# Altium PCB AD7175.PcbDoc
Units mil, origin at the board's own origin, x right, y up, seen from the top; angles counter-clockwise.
Board outline 2780 x 1750 mil, 2 copper layers (Top Layer, Bottom Layer); 97 components, 55 nets, 296 pads, 449 vias.
Unrouted connection lines stored in the file: 60.
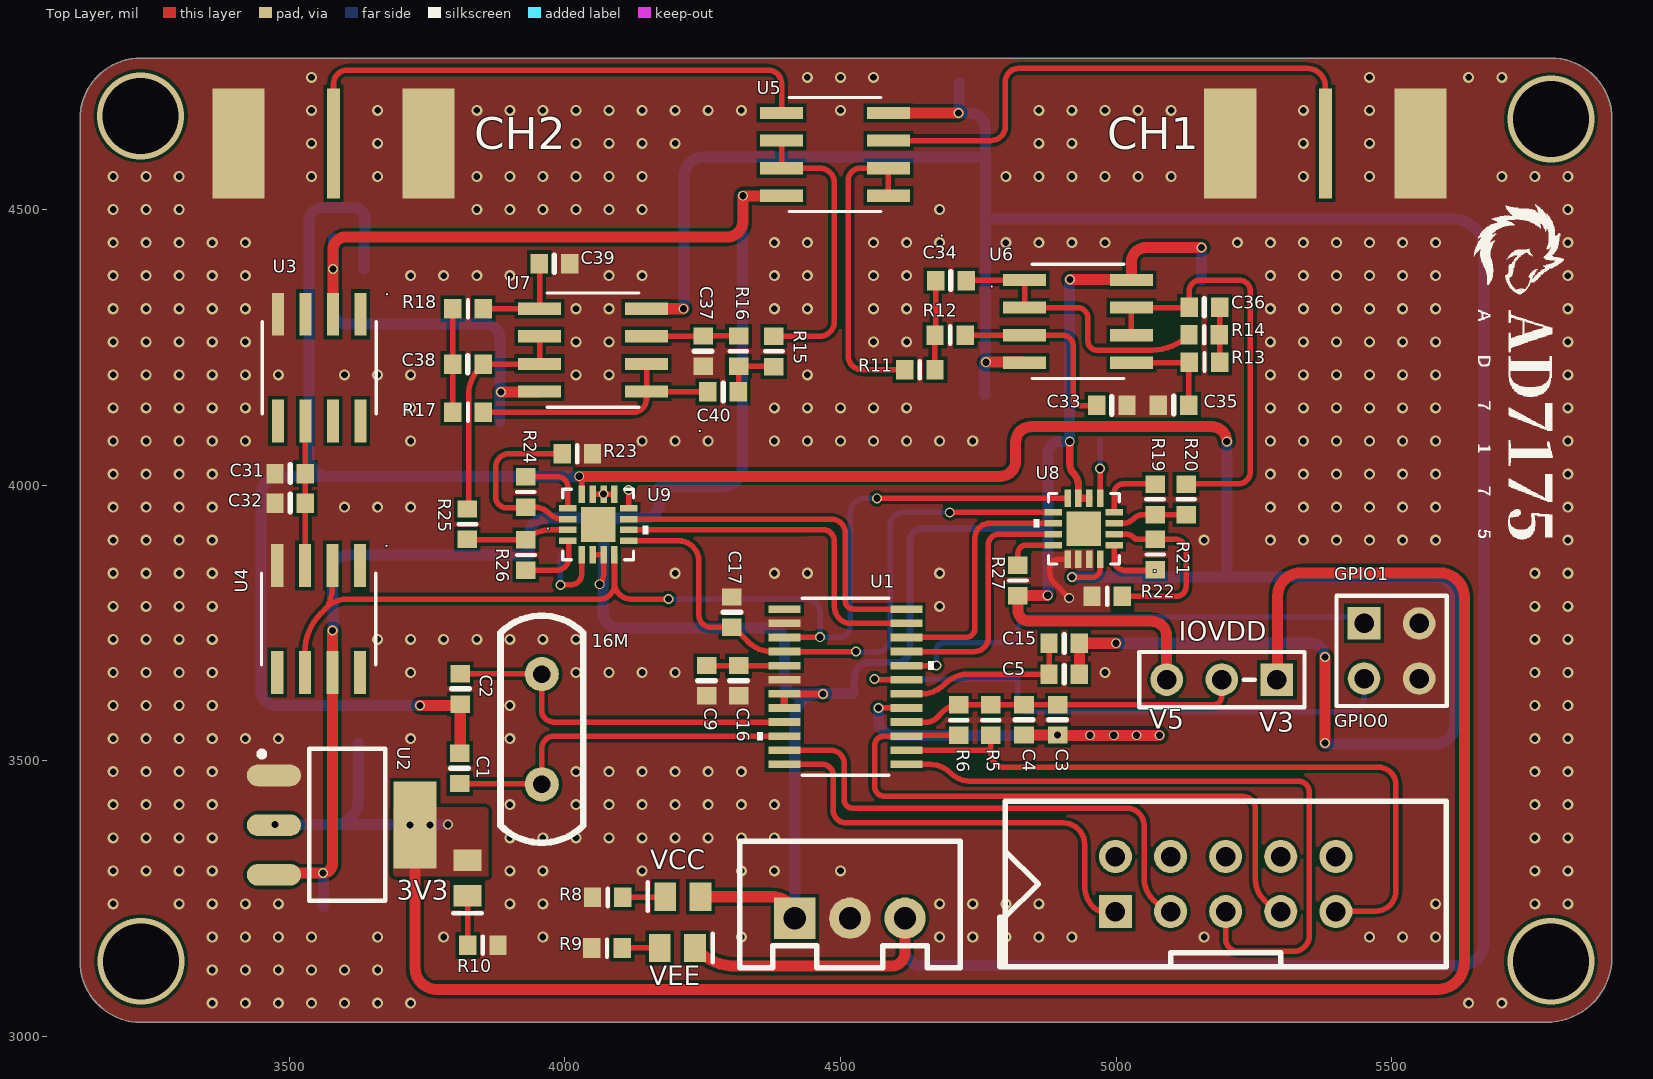
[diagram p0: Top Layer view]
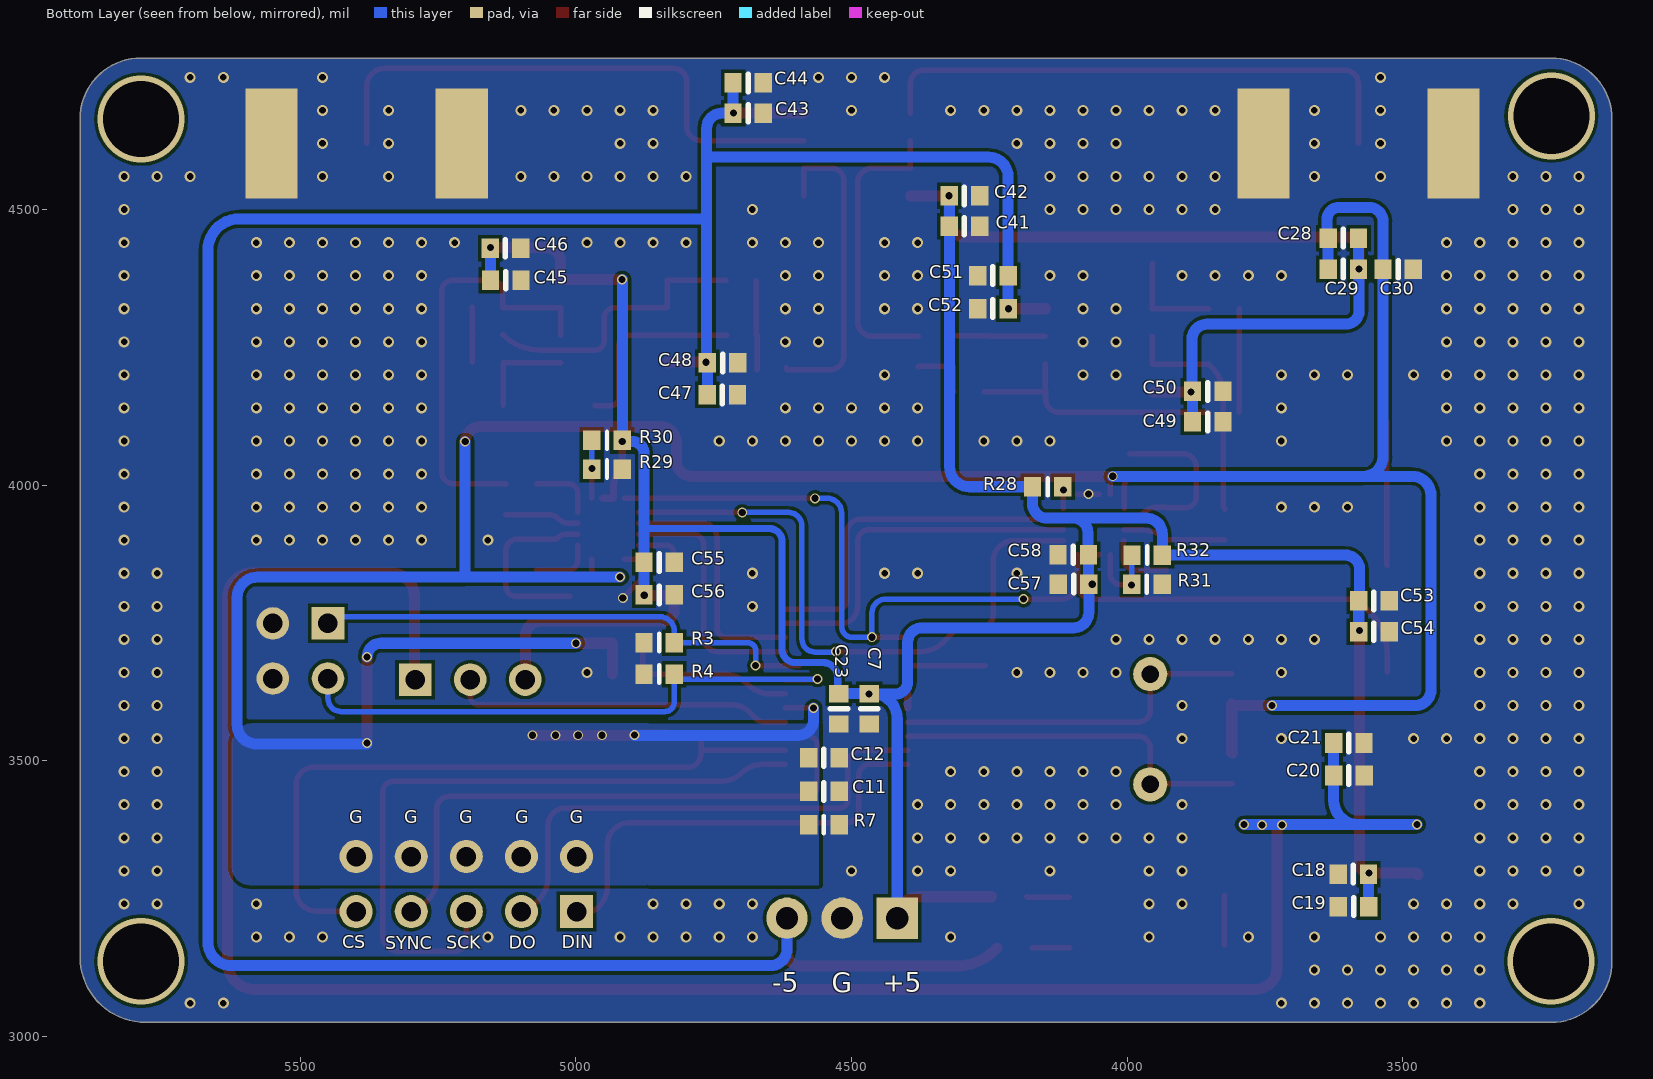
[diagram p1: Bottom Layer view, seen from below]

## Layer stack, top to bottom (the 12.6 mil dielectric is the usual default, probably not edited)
Top Solder: solder mask 0.4, Solder Resist, Dk 3.5
Top Layer: signal copper 1.4
Dielectric 1: dielectric 12.6, FR-4, Dk 4.8
Bottom Layer: signal copper 1.4
Bottom Solder: solder mask 0.4, Solder Resist, Dk 3.5

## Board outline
3120,3135.83 ccw(c3230.83,3135.83) 3230.83,3025 4085,3025 5781.01,3025 ccw(c5781.01,3143.99) 5900,3143.99 5900,4664.17 ccw(c5789.17,4664.17) 5789.17,4775 3230.83,4775 ccw(c3230.83,4664.17) 3120,4664.17

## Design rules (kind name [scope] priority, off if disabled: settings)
Clearance [All] p1: gap=6 ignorepadtopadclearanceinfootprint=FALSE except(0: Arc-Hole Track-Hole SMDPad-Hole THPad-Hole Via-Hole Fill-Hole Poly-Hole Region-Hole Text-Hole; 5: Arc-SMDPad Arc-THPad Track-SMDPad Track-THPad SMDPad-SMDPad SMDPad-THPad THPad-THPad)
PolygonConnect [All] p1: connectstyle=Direct reliefconductorwidth=10 reliefentries=4 polygonreliefangle="90 Angle" airgapwidth=10
RoutingVias [All] p1: holewidth=28 width=50 viastyle="Through Hole" minholewidth=28 minwidth=50 maxholewidth=28 maxwidth=50
SolderMaskExpansion [All] p1: expansion=4 istentingtop=FALSE
Width [All] p1: maxlimit=100 minlimit=10 preferedwidth=10
30 further rules are at their usual default settings.

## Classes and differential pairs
component class reference: C28 C29 C30 C31 C32 C53 C54 U3 U4
component class power: C7 C18 C19 C20 C21 C23 R8 R9 R10 U2
component class filter: C33 C34 C35 C36 C37 C38 C39 C40 C45 C46 C47 C48 C49 C50 C51 C52 R11 R12 R13 R14 R15 R16 R17 R18 U6 U7
component class fda: C55 C56 C57 C58 R19 R20 R21 R22 R23 R24 R25 R26 R27 R28 R29 R30 R31 R32 U8 U9
component class core: C1 C2 C3 C4 C5 C9 C11 C12 C15 C16 C17 C41 C42 C43 C44 CH1 CH2 IOVDD R3 R4 R5 R6 R7 U1 U5

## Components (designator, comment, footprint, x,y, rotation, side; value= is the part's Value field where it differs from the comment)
3V3 "LED" Led-0805_L 3823,3287 r270 top (schematic designator LED3)
16M "XTAL" XTAL-PB2-DIP 3966,3547 r270 top value=16M (schematic designator Y1)
C1 "Cap-S" C0603-L 3809,3486 r90 top value=20pF
C2 "Cap-S" C0603-L 3810,3630 r270 top value=20pF
C3 "Cap-S" C0603-L 4894,3574 r90 top value=1uF
C4 "Cap-S" C0603-L 4833,3574 r90 top value=100nF
C5 "Cap-S" C0603-L 4906,3657 r180 top value=1uF
C7 "Cap-S" C0603-L 4468,3594 r270 bottom value=1uF
C9 "Cap-S" C0603-L 4257,3645 r90 top value=1uF
C11 "Cap-S" C0603-L 4550,3444 r180 bottom value=1uF
C12 "Cap-S" C0603-L 4550,3505 r180 bottom value=100nF
C15 "Cap-S" C0603-L 4906,3713 r180 top value=100nF
C16 "Cap-S" C0603-L 4315,3645 r90 top value=100nF
C17 "Cap-S" C0603-L 4303,3769.44 r270 top value=100nF
C18 "Cap-S" C0603-L 3589.44,3294 r180 bottom value=1uF
C19 "Cap-S" C0603-L 3588.88,3235 r180 bottom value=100nF
C20 "Cap-S" C0603-L 3597.44,3473 r0 bottom value=100nF
C21 "Cap-S" C0603-L 3597.56,3532 r0 bottom value=1uF
C23 "Cap-S" C0603-L 4523,3594 r270 bottom value=100nF
C28 "Cap-S" C0603-L 3607.44,4448 r180 bottom value=4.7uF
C29 "Cap-S" C0603-L 3607.44,4392 r180 bottom value=100nF
C30 "Cap-S" C0603-L 3508,4392 r0 bottom value=100nF
C31 "Cap-S" C0603-L 3501.44,4021 r0 top value=4.7uF
C32 "Cap-S" C0603-L 3501.44,3967 r0 top value=100nF
C33 "Cap-S" C0603-L 4992.44,4145 r180 top value=13pF
C34 "Cap-S" C0603-L 4700.44,4371 r0 top value=130pF
C35 "Cap-S" C0603-L 5104.44,4145 r0 top value=10pF
C36 "Cap-S" C0603-L 5160.44,4323 r180 top value=119pF
C37 "Cap-S" C0603-L 4251,4243 r90 top value=13pF
C38 "Cap-S" C0603-L 3824,4219 r0 top value=119pF
C39 "Cap-S" C0603-L 3981,4402 r180 top value=10pF
C40 "Cap-S" C0603-L 4287,4169 r180 top value=130pF
C41 "Cap-S" C0603-L 4295,4470 r0 bottom value=100nF
C42 "Cap-S" C0603-L 4295,4525 r0 bottom value=1uF
C43 "Cap-S" C0603-L 4687.44,4675 r0 bottom value=100nF
C44 "Cap-S" C0603-L 4687.44,4730 r0 bottom value=1uF
C45 "Cap-S" C0603-L 5127.44,4372 r0 bottom value=100nF
C46 "Cap-S" C0603-L 5128,4430 r0 bottom value=1uF
C47 "Cap-S" C0603-L 4734.44,4164 r0 bottom value=100nF
C48 "Cap-S" C0603-L 4734,4222 r0 bottom value=1uF
C49 "Cap-S" C0603-L 3853.56,4115 r0 bottom value=100nF
C50 "Cap-S" C0603-L 3853.56,4170 r0 bottom value=1uF
C51 "Cap-S" C0603-L 4243.44,4380 r180 bottom value=100nF
C52 "Cap-S" C0603-L 4243.44,4320 r180 bottom value=1uF
C53 "Cap-S" C0603-L 3552,3790 r0 bottom value=100nF
C54 "Cap-S" C0603-L 3552,3734 r0 bottom value=1uF
C55 "Cap-S" C0603-L 4849,3860 r0 bottom value=100nF
C56 "Cap-S" C0603-L 4849,3801 r0 bottom value=1uF
C57 "Cap-S" C0603-L 4097,3820 r180 bottom value=100nF
C58 "Cap-S" C0603-L 4097.61,3873.31 r180 bottom value=1uF
CH1 "SMA" SMA1 5380,4620 r270 top
CH2 "SMA" SMA1 3580,4620 r270 top
GPIO1 "Header 2X2" HDR2X2 5450,3749 r270 top (schematic designator GPIO)
IOVDD "Jumper" JUMPER1x3 5192,3647 r180 top
POWER "Power-3P" SIPA03 4417,3214 r0 top
R3 "R" R0603-L 4849,3714 r180 bottom value=10K
R4 "R" R0603-L 4849,3657 r180 bottom value=10K
R5 "R" R0603-L 4773,3573.56 r90 top value=10K
R6 "R" R0603-L 4715,3573.56 r90 top value=10K
R7 "R" R0603-L 4550.12,3384 r0 bottom value=0R
R8 "R" R0603-L 4077.44,3252 r180 top value=1K
R9 "R" R0603-L 4076.44,3160 r180 top value=1K
R10 "R" R0603-L 3851,3165 r0 top value=600R
R11 "R" R0603-L 4644,4209 r0 top value=6.25K
R12 "R" R0603-L 4699,4272 r0 top value=177K
R13 "R" R0603-L 5160.44,4223 r0 top value=31.9K
R14 "R" R0603-L 5160,4273 r180 top value=31.9K
R15 "R" R0603-L 4379,4242.56 r270 top value=6.25K
R16 "R" R0603-L 4315,4243 r90 top value=177K
R17 "R" R0603-L 3824,4132 r0 top value=31.9K
R18 "R" R0603-L 3824,4320 r180 top value=31.9K
R19 "R" R0603-L 5071,3974 r90 top value=1K
R20 "R" R0603-L 5127,3974 r270 top value=1K
R21 "R" R0603-L 5071,3874 r270 top value=1K
R22 "R" R0603-L 4984,3798 r0 top value=1K
R23 "R" R0603-L 4022.44,4057 r180 top value=1K
R24 "R" R0603-L 3929,3987.56 r90 top value=1K
R25 "R" R0603-L 3823,3929 r270 top value=1K
R26 "R" R0603-L 3929,3873 r270 top value=1K
R27 "R" R0603-L 4822,3827 r270 top value=0R
R28 "R" R0603-L 4144,3997 r0 bottom value=0R
R29 "R" R0603-L 4943.56,4029 r180 bottom value=0R
R30 "R" R0603-L 4943.56,4081 r180 bottom value=0R
R31 "R" R0603-L 3964,3820 r180 bottom value=0R
R32 "R" R0603-L 3963.56,3873 r180 bottom value=0R
SPI "DC-10P" DC-10P 5198.94,3226 r180 top
U1 "AD7175-2BRUZ" RU_24_ADI 4509,3634 r0 top
U2 "AMS1117" SOT-223 3597,3383 r270 top
U3 "ADR4540ARZ" R_8_ADI 3554,4213 r270 top
U4 "AD8628ARZ" R_8_ADI 3553,3757 r270 top
U5 "ADA4084-2ARZ" R_8_ADI 4490,4600 r180 top
U6 "ADA4084-2ARZ" R_8_ADI 4931,4297 r0 top
U7 "ADA4084-2ARZ" R_8_ADI 4051,4245 r180 top
U8 "ADA4945-1" CP_16_22 4941.53,3920.79 r180 top
U9 "ADA4945-1" CP_16_22 4060.21,3928.53 r0 top
VCC "LED" Led-0805_L 4214,3253 r180 top (schematic designator LED1)
VEE "LED" Led-0805_L 4204,3160 r0 top (schematic designator LED2)

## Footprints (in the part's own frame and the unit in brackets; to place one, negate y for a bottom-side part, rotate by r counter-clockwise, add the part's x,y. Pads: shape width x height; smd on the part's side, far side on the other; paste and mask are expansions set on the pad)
C0603-L [mm] "贴片电容0603 高密度"
  rect 0.8x0.9 smd: 1(-0.7,0) 2(0.7,0)
  silkscreen extent 0,-0.39 0,0.41, body extent -0.8,-0.4 0.8,0.41, height 0.88
CP_16_22 [mm]
  rect 0.805x0.3 smd paste+0 mask+0: 1(-1.402,0.75) 2(-1.402,0.25) 3(-1.402,-0.25) 4(-1.402,-0.75) 9(1.402,-0.75) 10(1.402,-0.25) 11(1.402,0.25) 12(1.402,0.75)
  rect 0.3x0.805 smd paste+0 mask+0: 5(-0.75,-1.402) 6(-0.25,-1.402) 7(0.25,-1.402) 8(0.75,-1.402) 13(0.75,1.402) 14(0.25,1.402) 15(-0.25,1.402) 16(-0.75,1.402)
  rect 1.6x1.6 smd paste-0.787 mask+0: 17(0,0)
  silkscreen extent -1.63,-1.63 2.31,1.63, body extent 0,0 0.25,0.25, height 0.25
DC-10P [mil]
  rect 60x60 hole 35.43: 1(200,0)
  round 60 hole 35.43: 2(100,0) 3(0,0) 4(-100,0) 5(-200,0) 6(-200,-100) 7(-100,-100) 8(0,-100) 9(100,-100) 10(200,-100)
  silkscreen extent -400,-200 410,100, body extent -401,-233 401,123, height 357
HDR2X2 [mm] "Connector; Header; 2x2 Position"
  rect 1.5x1.5 hole 0.9: 1(0,0)
  round 1.5 hole 0.9: 2(0,2.54) 3(2.54,0) 4(2.54,2.54)
  silkscreen extent -1.27,-1.27 3.81,3.81
JUMPER1x3 [mm]
  rect 1.5x1.5 hole 0.9: 1(-2.54,0)
  round 1.5 hole 0.9: 2(0,0) 3(2.54,0)
  silkscreen extent -3.81,-1.27 3.81,1.27, body extent -3.81,-1.27 3.81,1.3, height 9.26
Led-0805_L [mm] "贴片LED0805-高密度"
  rect 1x1.3 smd: 1(-0.813,0) 2(0.813,0)
  silkscreen extent 1.63,-0.66 1.63,0.66, body extent -1.03,-0.44 1.03,0.47, height 0.85
R0603-L [mm] "贴片电阻0603 高密度"
  rect 0.8x0.9 smd: 1(-0.7,0) 2(0.7,0)
  silkscreen extent 0,-0.39 0,0.41, body extent -0.81,-0.43 0.79,0.39, height 0.53
R_8_ADI [mil]
  rect 78x22 smd paste+0 mask+0: 1(-97,75) 2(-97,25) 3(-97,-25) 4(-97,-75) 5(97,-75) 6(97,-25) 7(97,25) 8(97,75)
  silkscreen extent -84,-103 84,104, body extent -122,-99 122,99, height 69
RU_24_ADI [mil]
  rect 58x14 smd paste+0 mask+0: 1(-111,140.75) 2(-111,115.16) 3(-111,89.57) 4(-111,63.98) 5(-111,38.39) 6(-111,12.8) 7(-111,-12.8) 8(-111,-38.39) 9(-111,-63.98) 10(-111,-89.57) 11(-111,-115.16) 12(-111,-140.75) 13(111,-140.75) 14(111,-115.16) 15(111,-89.57) 16(111,-63.98) 17(111,-38.39) 18(111,-12.8) 19(111,12.8) 20(111,38.39) 21(111,63.98) 22(111,89.57) 23(111,115.16) 24(111,140.75)
  silkscreen extent -160,-160 160,160, body extent -126,-156 126,156, height 47
SIPA03 [mil]
  rect 75x75 hole 40: 1(0,0)
  round 75 hole 40: 2(100,0) 3(200,0)
  silkscreen extent -100,-90 300,140, body extent -96,-99 298,137, height 276
SMA1 [mil]
  rect 200x24 smd: 1(0,0)
  rect 200x95 smd: 2(0,-172.5) 2(0,172.5)
  rect 200x95 smd far side: 2(0,-172.5)
  rect 200x95 smd far side mask+4: 2(0,172.5)
  body extent -475,-187 87,187, height 171
SOT-223 [mm]
  oval 1x2.5 smd: 1(-2.29,-3.175) 2(0,-3.175) 3(2.29,-3.175)
  rect 4x2 smd: 2(0,3.325)
  silkscreen extent -3.52,-3.86 3.48,1.96, body extent -3.25,-3.2 3.25,3.76, height 1.66
XTAL-PB2-DIP [mil]
  round 62 hole 32: 1(-110,-8) 2(90,-8)
  silkscreen extent -216,-83 196,67, body extent -234,-99 212,85, height 142

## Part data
3V3 VCC VEE: "发光二极管"
16M: "晶振"
C1 C2 C3 C4 C5 C7 C9 C11 C12 C15 C16 C17 C18 C19 C20 C21 C23 C28 C29 C30 C31 C32 C33 C34 C35 C36 C37 C38 C39 C40 C41 C42 C43 C44 C45 C46 C47 C48 C49 C50 C51 C52 C53 C54 C55 C56 C57 C58: "贴片瓷片电容"
GPIO1: "Header, 2-Pin, Dual row"
IOVDD: library part Jumper1*3
POWER: "供电端子"
R3 R4 R5 R6 R7 R8 R9 R10 R11 R12 R13 R14 R15 R16 R17 R18 R19 R20 R21 R22 R23 R24 R25 R26 R27 R28 R29 R30 R31 R32: library part Res, "贴片电阻"
U1 U3 U4 U5 U6 U7: "No Description Available", Mfr_Name="Analog Devices Inc"

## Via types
v1: diameter 20, hole 12, Top Layer to Bottom Layer, 402 vias
v2: diameter 18, hole 13, Top Layer to Bottom Layer, 43 vias
v3: diameter 157.48, hole 137.8, Top Layer to Bottom Layer, 4 vias

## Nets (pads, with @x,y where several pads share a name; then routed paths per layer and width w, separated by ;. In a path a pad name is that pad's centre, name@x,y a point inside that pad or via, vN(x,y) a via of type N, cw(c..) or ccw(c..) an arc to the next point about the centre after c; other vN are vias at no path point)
3V3: 3V3.1 C20.2 C21.2 IOVDD.1 U2.2 | length 3903.6
  Top Layer w20: U2.2@3727.91,3383 3727.91,3124.09 ccw(c3767,3124.09) 3767,3085 5584,3085 ccw(c5584,3133) 5632,3133 5632,3796.57 ccw(c5587.91,3796.57) 5587.91,3840.66 5335.66,3840.66 ccw(c5335.66,3798) 5293,3798 5293,3648 cw(c5292,3648) IOVDD.1
  Bottom Layer w20: v2(3474,3384) 3581,3384 ; C21.2 3625,3532 C20.2 3625,3428 cw(c3581,3428) 3581,3384 ; v2(3788,3384) 3581,3384
  other v2: 3719,3383 3755,3383
AIN0: U1.21 U8.11 | length 460
  Top Layer w10: U1.21 4742.98,3697.98 ccw(c4742.98,3723) 4768,3723 4768,3891 cw(c4787.94,3891) 4787.94,3910.94 U8.11
AIN1: U1.22 U8.10 | length 454.9
  Top Layer w10: U1.22 4727.57,3723.57 ccw(c4727.57,3740) 4744,3740 4744,3904 cw(c4770.63,3904) 4770.63,3930.63 U8.10
AIN2: U1.23 U9.10 | length 653.1
  Top Layer w10: U9.10 4439,3918.69 4439,3919 4468,3919 cw(c4468,3898) 4489,3898 4489,3779.16 ccw(c4519.16,3779.16) 4519.16,3749 4620,3749 U1.23
AIN3: U1.24 U9.11 | length 650.7
  Top Layer w10: U9.11 4482.63,3938.37 cw(c4482.63,3912) 4509,3912 4509,3789.32 ccw(c4523.32,3789.32) 4523.32,3775 4620,3775 U1.24
AVSS: C7.2 C9.1 C11.2 C12.2 C16.1 C17.1 C18.1 C19.1 C20.1 C21.1 C23.2 C30.1 C31.1 C32.1 C33.1 C35.1 C37.1 C39.1 C41.1 C42.1 C43.1 C44.1 C45.1 C46.1 C47.1 C48.1 C49.1 C50.1 C51.1 C52.1 C53.1 C54.1 C55.1 C56.1 C57.1 C58.1 CH1.2 CH2.2 GPIO1.2 GPIO1.4 POWER.2 R3.1 R4.1 R7.1 R8.2 R9.2 R10.2 R22.1 R23.1 R29.2 R31.2 U1.2 U1.6 U2.1 U3.4 U4.4 U8.13 U8.14 U8.15 U9.13 U9.14 U9.15 | length 148.7
  Top Layer w10: U9.15 v2(4070.06,3983.74) U9.13 ; U8.13 4895.57,3865.57 ccw(c4895.57,3850) 4880,3850 4880,3840 ccw(c4904.14,3840) 4887.07,3822.93 v2(4915,3795)
  other v1: 3360,3060 3420,3060 3480,3060 3540,3060 3600,3060 3660,3060 3720,3060 5640,3060 5700,3060 3360,3120 3420,3120 3480,3120 3540,3120 3600,3120 3660,3120 3360,3180 3420,3180 3480,3180 3540,3180 3660,3180 3780,3180 3960,3180 4320,3180 4680,3180 4740,3180 4800,3180 4860,3180 4920,3180 5160,3180 5460,3180 5520,3180 5580,3180 3180,3240 3300,3240 3360,3240 3420,3240 3480,3240 3900,3240 3960,3240 4680,3240 4740,3240 4800,3240 4860,3240 5580,3240 5760,3240 5820,3240 3180,3300 3240,3300 3300,3300 3360,3300 3900,3300 3960,3300 4140,3300 4320,3300 4380,3300 4500,3300 5760,3300 5820,3300 3180,3360 3240,3360 3300,3360 3360,3360 3900,3360 3960,3360 4020,3360 4080,3360 4140,3360 4200,3360 4260,3360 4320,3360 4380,3360 5760,3360 5820,3360 3180,3420 3240,3420 3300,3420 3360,3420 3900,3420 4020,3420 4080,3420 4140,3420 4200,3420 4260,3420 4320,3420 4380,3420 5760,3420 5820,3420 3180,3480 3240,3480 3300,3480 3360,3480 4020,3480 4080,3480 4140,3480 4200,3480 4260,3480 4320,3480 5760,3480 5820,3480 3180,3540 3240,3540 3300,3540 3360,3540 3420,3540 3480,3540 3720,3540 3900,3540 5760,3540 5820,3540 3180,3600 3240,3600 3300,3600 3360,3600 3900,3600 5760,3600 5820,3600 3180,3660 3240,3660 3300,3660 3360,3660 3720,3660 4020,3660 4080,3660 4140,3660 4200,3660 4980,3660 5760,3660 5820,3660 3180,3720 3240,3720 3300,3720 3360,3720 3660,3720 3720,3720 3780,3720 3840,3720 3900,3720 3960,3720 4020,3720 5760,3720 5820,3720 3180,3780 3240,3780 3300,3780 3360,3780 4680,3780 5760,3780 5820,3780 3180,3840 3240,3840 3300,3840 3360,3840 4200,3840 4380,3840 4440,3840 4680,3840 5760,3840 5820,3840 3180,3900 3240,3900 3300,3900 3360,3900 5160,3900 5280,3900 5340,3900 5400,3900 5460,3900 5520,3900 5580,3900 5820,3900 3180,3960 3240,3960 3300,3960 3360,3960 3600,3960 3660,3960 3720,3960 5280,3960 5340,3960 5400,3960 5460,3960 5520,3960 5580,3960 5820,3960 3180,4020 3240,4020 3300,4020 3360,4020 5280,4020 5340,4020 5400,4020 5460,4020 5520,4020 5580,4020 5820,4020 3180,4080 3240,4080 3300,4080 3360,4080 3420,4080 3720,4080 4140,4080 4200,4080 4260,4080 4380,4080 4440,4080 4500,4080 4560,4080 4620,4080 4680,4080 4740,4080 5280,4080 5340,4080 5400,4080 5460,4080 5520,4080 5580,4080 5820,4080 3180,4140 3240,4140 3300,4140 3360,4140 3420,4140 3720,4140 4380,4140 4440,4140 4500,4140 4560,4140 4620,4140 5280,4140 5340,4140 5400,4140 5460,4140 5520,4140 5580,4140 5820,4140 3180,4200 3240,4200 3300,4200 3360,4200 3420,4200 3480,4200 3600,4200 3660,4200 3720,4200 4020,4200 4080,4200 4440,4200 5280,4200 5340,4200 5400,4200 5460,4200 5520,4200 5580,4200 5820,4200 3180,4260 3240,4260 3300,4260 3360,4260 3420,4260 4020,4260 4080,4260 4560,4260 4620,4260 5280,4260 5340,4260 5400,4260 5460,4260 5520,4260 5580,4260 5820,4260 3180,4320 3240,4320 3300,4320 3360,4320 3420,4320 4020,4320 4080,4320 4380,4320 4440,4320 4560,4320 4620,4320 5280,4320 5340,4320 5400,4320 5460,4320 5520,4320 5580,4320 5820,4320 3180,4380 3240,4380 3300,4380 3360,4380 3420,4380 3720,4380 3780,4380 3840,4380 3900,4380 4080,4380 4140,4380 4380,4380 4440,4380 4560,4380 4620,4380 5280,4380 5340,4380 5400,4380 5460,4380 5520,4380 5580,4380 5820,4380 3180,4440 3240,4440 3300,4440 3360,4440 3420,4440 4380,4440 4440,4440 4560,4440 4620,4440 4680,4440 4800,4440 4860,4440 4920,4440 4980,4440 5220,4440 5280,4440 5340,4440 5400,4440 5460,4440 5520,4440 5580,4440 5820,4440 3180,4500 3240,4500 3300,4500 3840,4500 3900,4500 3960,4500 4020,4500 4080,4500 4140,4500 4680,4500 5820,4500 3180,4560 3240,4560 3300,4560 3540,4560 3660,4560 3840,4560 3900,4560 3960,4560 4020,4560 4080,4560 4140,4560 4800,4560 4860,4560 4920,4560 4980,4560 5040,4560 5100,4560 5340,4560 5460,4560 5700,4560 5760,4560 5820,4560 3540,4620 3660,4620 4020,4620 4080,4620 4140,4620 4200,4620 4860,4620 4920,4620 5340,4620 5460,4620 3540,4680 3660,4680 3840,4680 3900,4680 3960,4680 4020,4680 4080,4680 4140,4680 4200,4680 4260,4680 4320,4680 4500,4680 4860,4680 4920,4680 4980,4680 5040,4680 5100,4680 5340,4680 5460,4680 3540,4740 4440,4740 4500,4740 4560,4740 5460,4740 5640,4740 5700,4740
CH1_Filter: C36.2 R20.1 U6.6 U6.7 | length 775.5
  Top Layer w10: U6.6 U6.7 5131.88,4322 ccw(c5131.88,4323) C36.2 5132.88,4351.88 cw(c5153,4351.88) 5153,4372 5223,4372 cw(c5223,4351) 5244,4351 5244,4025 cw(c5221,4025) 5221,4002 5127,4002 R20.1
CH1_Foller: R11.1 U5.1 U5.2 | length 575
  Top Layer w10: U5.1 U5.2 4536,4575 ccw(c4536,4553) 4514,4553 4514,4235 ccw(c4540,4235) 4540,4209 R11.1 ccw(c4612.68,4212.76) R11.1@4618,4212.76
CH2_Filter: C38.2 R25.1 U7.6 U7.7 | length 423.9
  Top Layer w10: R25.1 ccw(c3818.17,3961.39) 3825,3961.39 3825,4163 cw(c3896.08,4163) 3845.82,4213.26 C38.2 3953,4219 ccw(c3953,4220) U7.7 U7.6
CH2_Foller: R15.1 U5.6 U5.7 | length 537.9
  Top Layer w10: R15.1 4379,4270 4462,4270 ccw(c4462,4297) 4489,4297 4489,4548 ccw(c4462,4548) 4462,4575 U5.7 U5.6
CS: R5.1 SPI.5 U1.14 | length 1276.3
  Top Layer w10: U1.14 4773,3518.84 ; R5.1 4773,3518.84 ; SPI.5 cw(c5399.94,3226) 5399.94,3227 5471,3227 ccw(c5471,3264) 5508,3264 5508,3456 ccw(c5476,3456) 5476,3488 4798,3488 cw(c4798,3513) 4773,3513 4773,3518.84
DGND: C1.2 C2.2 C3.1 C4.1 C5.1 C11.1 C12.1 C15.1 C28.1 C29.1 C30.2 R7.2 SPI.6 SPI.7 SPI.8 SPI.9 SPI.10 U1.17 U8.16 U9.16 | length 6271.1
  Top Layer w10: v2(4026,4016) cw(c4014.69,4004.69) 4030.69,4004.69 U9.16 ; v2(4569,3595.61) U1.17 ; v2(4920,3833) 4957,3833 ccw(c4957,3847.06) 4971.06,3847.06 U8.16
  Top Layer w20: v2(3737,3600) 3807.56,3600 C2.2 3810,3514.56 cw(c3809,3514.56) C1.2 ; v2(4026,4016) 4790,4016 ccw(c4790,4044) 4818,4044 4818,4078 cw(c4846,4078) 4846,4106 5174,4106 cw(c5174,4079) v2(5201,4079) ; C4.1 v2(4894,3546.44) 4894.44,3546 v2(4953,3546) v2(4996,3546) v2(5037,3546) v2(5079,3546) ; C5.1 C15.1 v2(5000,3713) ; v2(5379,3532) v2(5379,3688)
  Bottom Layer w20: C29.1 C28.1 ccw(c3635,4450) 3637,4450 3637,4482 ccw(c3615,4482) 3615,4504 3561,4504 ccw(c3561,4478.56) 3535.56,4478.56 C30.2 3535.56,4051.44 ccw(c3571,4051.44) 3571,4016 ; v2(3737,3600) 3477,3600 cw(c3477,3628.51) 3448.49,3628.51 3448.49,3981.49 cw(c3483,3981.49) 3483,4016 3571,4016 ; v2(4026,4016) 3571,4016 ; v2(4569,3595.61) 4569,3573 ccw(c4596,3573) 4596,3546 4894,3546 v2(4894,3546.44) ; v2(4920,3833) 5202,3833 ; v2(5000,3713) 5354,3713 cw(c5354,3688) v2(5379,3688) ; v2(5201,4079) 5201,3834 ccw(c5202,3834) 5202,3833 ; v2(5379,3532) ccw(c5381,3532) 5381,3530 5579,3530 ccw(c5579,3566) 5615,3566 5615,3796 ccw(c5578,3796) 5578,3833 5202,3833
DIN: SPI.1 U1.12 | length 815.3
  Top Layer w10: U1.12 4466.81,3493.25 cw(c4466.81,3473.06) 4487,3473.06 4487,3410 ccw(c4510,3410) 4510,3387 4904.04,3387 cw(c4904.04,3348.04) 4943,3348.04 4943,3272.63 ccw(c4997.63,3272.63) 4959,3234 ccw(c4978.31,3253.31) 4978.31,3226 SPI.1
DOUT: SPI.2 U1.11 | length 937.7
  Top Layer w10: U1.11 4482.16,3518.84 cw(c4482.16,3494) 4507,3494 4507,3428 ccw(c4521,3428) 4521,3414 5019,3414 cw(c5019,3382) 5051,3382 5051,3286.63 ccw(c5105.63,3286.63) 5067,3248 SPI.2@5081.97,3233.03 ; SPI.2@5081.98,3233.02 ccw(c5098.94,3249.99) SPI.2
GPIO0: GPIO1.3 R4.2 U1.19 | length 1062
  Top Layer w10: v2(4562,3648) ccw(c4563.2,3648) 4563.2,3646.8 U1.19
  Bottom Layer w10: v2(4562,3648) 4812.44,3648 ccw(c4812.44,3657) R4.2 4821.44,3606.56 ccw(c4839,3606.56) 4839,3589 5426,3589 ccw(c5426,3613) 5450,3613 GPIO1.3
GPIO1: GPIO1.1 R3.2 U1.20 | length 930.6
  Top Layer w10: U1.20@4595.94,3672.39 U1.20 v2(4674,3672.39) v2@4674,3672
  Bottom Layer w10: v2(4674,3672.39) 4674,3700 cw(c4688,3700) 4688,3714 R3.2 4821.44,3734.44 cw(c4848,3734.44) 4848,3761 5438,3761 GPIO1.1
IOVDD: C3.2 C4.2 IOVDD.2 R5.2 R6.2 U1.16 | length 633
  Top Layer w10: U1.16 4658.57,3570.02 ccw(c4658.57,3590.43) 4672.99,3575.99 4686.18,3589.18 cw(c4715,3560.36) R6.2 ; R6.2@4703.84,3598.9 cw(c4715,3571.96) 4706.34,3599.8 cw(c4715,3571.96) R6.2 ; IOVDD.2 5192,3617 cw(c5176.56,3617) 5176.56,3601.56 C3.2 C4.2 4833,3601.12 R5.2 R6.2
NetC31_2: C31.2 C32.2 U3.6 U4.3 | length 262.3
  Top Layer w10: U4.3 ccw(c3525.59,3856.41) 3529,3856.41 C32.2 C31.2 U3.6
NetC33_2: C33.2 R12.2 U6.3 | length 352.3
  Top Layer w10: R12.2 U6.3 4903,4272 cw(c4903,4253) 4922,4253 4922,4159 ccw(c4937,4159) 4937,4144 4963.88,4144 ccw(c4963.88,4145) C33.2
NetC34_1: C34.1 R11.2 R12.1 | length 162.9
  Top Layer w10: R11.2 4671.44,4209 R12.1 ccw(c4671.44,4273.44) 4672.88,4273.44 C34.1
NetC34_2: C34.2 R14.2 U6.1 U6.2 | length 524.5
  Top Layer w10: C34.2 cw(c4729,4371) 4729,4372 U6.1 U6.2 4930,4322 cw(c4930,4303) 4949,4303 4949,4261 ccw(c4965,4261) 4965,4245 5064.84,4245 ccw(c5064.84,4340.6) R14.2
NetC35_2: C35.2 R13.1 U6.5 | length 181
  Top Layer w10: U6.5 5132,4222 C35.2
NetC36_1: C36.1 R13.2 R14.1 | length 100.4
  Top Layer w10: R14.1 R14.1@5188,4273 ; R13.2 R14.1@5188,4273 ; C36.1 R14.1@5188,4273
NetC37_2: C37.2 R16.2 U7.3 | length 167.6
  Top Layer w10: U7.3 4251,4270 C37.2 R16.2
NetC38_1: C38.1 R17.1 R18.2 | length 188
  Top Layer w10: R17.1 C38.1 R18.2
NetC39_2: C39.2 R18.1 U7.5 | length 185
  Top Layer w10: R18.1 U7.5 3954,4402 C39.2
NetC40_1: C40.1 R15.2 R16.1 | length 111.3
  Top Layer w10: C40.1 4315,4169 R16.1 4379,4215.44 R15.2
NetC40_2: C40.2 R17.2 U7.1 U7.2 | length 485.9
  Top Layer w10: R17.2 4123.31,4132 ccw(c4123.31,4156.66) 4147.98,4156.66 U7.1 ; U7.2 U7.1 ; C40.2 4149,4169 cw(c4149,4170) U7.1
NetCH1_1: CH1.1 U5.3 | length 1024.4
  Top Layer w10: U5.3 4773,4625 ccw(c4773,4651) 4799,4651 4799,4732 cw(c4823,4732) 4823,4756 5347,4756 cw(c5347,4723) 5380,4723 CH1.1
NetCH2_1: CH2.1 U5.5 | length 1003
  Top Layer w10: CH2.1 3580,4728 cw(c3605,4728) 3605,4753 4369,4753 cw(c4369,4729) 4393,4729 U5.5
NetLED1_2: R8.1 VCC.2 | length 77.3
  Top Layer w10: R8.1 4179.59,3252 ccw(c4179.59,3255.41) VCC.2
NetLED2_1: R9.1 VEE.1 | length 68
  Top Layer w10: R9.1 VEE.1
NetLED3_2: 3V3.2 R10.1 | length 90.1
  Top Layer w10: 3V3.2 cw(c3821.94,3253.94) 3823.44,3253.94 R10.1
NetR19_1: R19.1 R20.2 U8.3 | length 134.5
  Top Layer w10: U8.3 5011.79,3930.63 ccw(c5011.79,3959.21) 5032,3939 cw(c5049.96,3921.04) 5049.96,3946.44 R19.1 R20.2
NetR19_2: R19.2 U8.4 | length 119.4
  Top Layer w10: U8.4 4996.74,3985.74 cw(c5013,3985.74) 5013,4002 5071,4002 R19.2
NetR21_1: R21.1 R22.2 U8.2 | length 335.6
  Top Layer w10: U8.2 5017.65,3910.94 cw(c5017.65,3890.65) 5032,3905 ccw(c5040.31,3913.31) 5040.31,3901.56 R21.1 5107.44,3901.56 cw(c5107.44,3882) 5127,3882 5127,3816 cw(c5109,3816) 5109,3798 R22.2
NetR21_2: R21.2 U8.1 | length 113.1
  Top Layer w10: U8.1 4996.74,3864.26 ccw(c5016,3864.26) 5016,3845 5069.56,3845 ccw(c5069.56,3846.44) R21.2
NetR23_2: R23.2 R24.1 U9.2 | length 336.9
  Top Layer w10: R23.2 3899,4057 ccw(c3899,4032) 3874,4032 3874,3979 ccw(c3894,3979) 3894,3959 3928,3959 ccw(c3928,3960) R24.1 3944.44,3960 cw(c3944.44,3922.44) 3971,3949 ccw(c3996.66,3974.66) 3996.66,3938.37 U9.2
NetR24_2: R24.2 U9.1 | length 125.3
  Top Layer w10: R24.2 3986.88,4015.12 cw(c3986.88,3997) 4005,3997 U9.1
NetR25_2: R25.2 R26.1 U9.3 | length 187
  Top Layer w10: R25.2@3823,3901 3927.94,3901 cw(c3927.94,3899.49) R26.1 cw(c3972.76,3856.8) 3972.76,3918.69 U9.3
NetR26_2: R26.2 U9.4 | length 123
  Top Layer w10: R26.2 3984.44,3845.44 ccw(c3984.44,3868) 4007,3868 4007,3897 ccw(c4005,3897) U9.4
NetR27_1: R27.1 U8.12 | length 94.5
  Top Layer w10: R27.1 4822,3876 cw(c4837.26,3876) 4837.26,3891.26 U8.12
NetR28_1: R28.1 U9.12 | length 32.9
  Top Layer w10: U9.12 v2(4115.43,3991)
NetR29_1: R29.1 R30.1 U8.5 | length 105.1
  Top Layer w10: v2@4971,4030 v2(4971.06,4030) U8.5
  Bottom Layer w10: v2(4971.06,4030) R30.1 R30.1
NetR31_1: R31.1 R32.1 U9.5 | length 138.6
  Top Layer w10: v2(3992,3819) 4010,3819 ccw(c4010,3839.68) 4030.68,3839.68 U9.5
  Bottom Layer w10: R32.1 3991.12,3819.88 ccw(c3992,3819.88) v2(3992,3819)
REF_2V5: C17.2 U1.4 U8.9 U9.9 | length 1151.6
  Top Layer w10: U9.9 4205.94,3899 cw(c4205.94,3861.94) 4243,3861.94 4243,3764 ccw(c4265,3764) 4265,3742 4303,3742 C17.2 cw(c4303,3734.35) 4308.31,3739.69 4333,3715 ccw(c4374.1,3756.1) 4374.1,3697.98 U1.4 v2(4527.98,3697.98) ; v2@4698,3950 v2(4698.31,3950.32) U8.9
  Bottom Layer w10: v2(4527.98,3697.98) ccw(c4528.95,3697.98) 4528.95,3697 4566,3697 ccw(c4566,3721) 4590,3721 4590,3926 cw(c4614.31,3926) 4614.31,3950.32 v2(4698.31,3950.32)
REF_4V096: U1.3 U4.2 U4.6 U8.8 U9.8 | length 2048.1
  Top Layer w10: U4.6 3528,3696.56 cw(c3628,3696.56) 3557.29,3767.27 3568.32,3778.3 ; U4.2 3578,3816.94 cw(c3496.06,3816.94) 3568.32,3778.3 ; v2(4188,3793) 4120,3793 cw(c4120,3823.26) 4089.99,3819.36 ; U1.3 4461.95,3723.57 ccw(c4461.95,3725.05) v2(4463,3724) ; v2(4566,3976) U8.8 ; 3568.32,3778.3 cw(c3603.81,3742.8) 3603.81,3793 4063,3793 ccw(c4063,3820) 4089.99,3819.36 ; 4089.99,3819.36 ccw(c4063,3820) 4090,3820 4090,3873.06 U9.8 4089.74,3823.26 ccw(c4120,3823.26) 4089.99,3819.36
  Bottom Layer w10: v2(4188,3793) 4438,3793 cw(c4438,3768) 4463,3768 v2(4463,3724) 4499,3724 ccw(c4499,3743) 4518,3743 4518,3950 cw(c4544,3950) 4544,3976 v2(4566,3976)
REGCAPA: C9.2 C16.2 U1.5 | length 141.1
  Top Layer w10: C9.2 C16.2 4315.17,3672.39 U1.5
REGCAPD: C5.2 C15.2 U1.18 | length 324.2
  Top Layer w10: U1.18 4648.74,3621.2 4648.8,3621.2 ccw(c4648.8,3671.65) 4668.11,3625.04 ccw(c4641.68,3688.85) 4690.52,3640.02 4690.55,3640.05 cw(c4731.53,3599) 4731.53,3657 4731.59,3657 C5.2 C15.2
SCLK: SPI.3 U1.13 | length 1241.2
  Top Layer w10: U1.13 4661.56,3493.25 cw(c4661.56,3439.14) 4699.83,3477.4 ccw(c4734.6,3512.17) 4734.6,3463 5330,3463 cw(c5330,3442) 5351,3442 5351,3183 cw(c5322,3183) 5322,3154 5221,3154 cw(c5221,3176) 5199,3176 5199,3226 SPI.3
SYNC: R6.1 SPI.4 U1.15 | length 1159.4
  Top Layer w10: R6.1 4621.57,3546 ccw(c4621.57,3544.43) U1.15 4579.43,3544.43 ccw(c4579.43,3527) 4562,3527 4562,3453 ccw(c4580,3453) 4580,3435 5230,3435 cw(c5230,3412) 5253,3412 5253,3284.21 ccw(c5304.21,3284.21) 5267.99,3248.01 5283.68,3232.32 ccw(c5298.94,3247.58) SPI.4
VCC: C7.1 C18.2 C19.2 C23.1 C28.2 C29.2 C41.2 C42.2 C45.2 C46.2 C49.2 C50.2 C53.2 C54.2 C55.2 C56.2 C57.2 C58.2 IOVDD.3 POWER.1 R27.2 R28.2 R30.2 R32.2 U1.7 U1.8 U2.3 U3.2 U4.7 U5.8 U6.8 U7.8 U8.6 U8.7 U9.6 U9.7 VCC.1 | length 7464.1
  Top Layer w10: U9.6 U9.7 4070.06,3840.06 4070,3840 4070,3836.9 cw(c4046.1,3836.9) v2(4063,3820)
  Top Layer w13: U7.8@3953,4169 ccw(c3953,4170) U7.8 ; U1.8 U1.7 v2(4468,3621.2) ; v2(4916,4079) 4916,4037.9 ccw(c4939.9,4037.9) 4923,4021 cw(c4902.03,4000.03) 4931.69,4000.03 U8.7 U8.6
  Top Layer w20: U2.3 cw(c3475.16,3292.84) 3475.16,3296 v2(3561,3296) ccw(c3561,3313) 3578,3313 U4.7 v2(3578,3736) ; U3.2 v2(3579,4392) 3579,4427 cw(c3602,4427) 3602,4450 4294,4450 ccw(c4294,4479) 4323,4479 v2(4323,4525) U5.8 ; v2(3884,4169) U7.8@3953,4169 ; VCC.1 4378,3253 cw(c4378,3214) POWER.1 ; v2@4468,3621 v2(4468,3621.2) ; v2(4876,3800) 4822,3800 R27.2 4822,3773 ccw(c4842,3773) 4842,3753 5064,3753 cw(c5064,3725) 5092,3725 IOVDD.3 ; v2(4916.5,4373) 5027,4373 U6.8 5028,4405 cw(c5054,4405) 5054,4431 v2(5155,4431)
  Bottom Layer w13: C53.2@3578,3791.56 ccw(c3579.56,3791.56) C53.2 ; C50.2@3882,4171 ccw(c3884,4171) v2(3884,4169) ; C58.2 ccw(c4070.06,3874.26) C58.2@4071,3874.26 ; C23.1 ccw(c4523,3623.56) 4525,3623.56 4525,3651 cw(c4552,3651) 4552,3678 4602,3678 ccw(c4602,3702) 4626,3702 4626,3898 cw(c4649,3898) 4649,3921 4876.56,3921
  Bottom Layer w20: C19.2 3561.88,3235 C18.2 ; C53.2@3578,3791.56 3578,3847 cw(c3604,3847) 3604,3873 R32.2 3936,3911 cw(c3965,3911) 3965,3940 4145,3940 ccw(c4145,3966.56) 4171.56,3966.56 R28.2 4286,3997 ccw(c4286,4033) 4322,4033 4322,4470 C41.2 C42.2 ; v2(3579,4392) 3579,4316 ccw(c3603,4316) 3603,4292 3855,4292 cw(c3855,4265) 3882,4265 C50.2@3882,4171 ; C54.2 C53.2 ; C29.2 C28.2 ; C49.2 C50.2 ; C58.2 4070.06,3820 C57.2 4069.44,3768.56 ccw(c4097,3768.56) 4097,3741 4372,3741 cw(c4372,3715) 4398,3715 4398,3643 ccw(c4420,3643) 4420,3621 C7.1@4454.37,3621 ; C58.2@4071,3874.26 4071,3914 cw(c4097,3914) 4087,3938 ; POWER.1 4417,3576.21 cw(c4462.52,3576.21) C7.1@4454.37,3621 ; C23.1 C7.1 4460.56,3621.56 ccw(c4460.56,3587) C7.1@4454.37,3621 ; C56.2 C55.2 4876.56,3921 4876.56,4057.56 cw(c4898,4057.56) 4898,4079 v2(4916,4079) ; R30.2 v2@4916,4373 ; C45.2 5155,4430 C46.2
VEE: C43.2 C44.2 C47.2 C48.2 C51.2 C52.2 POWER.3 U5.4 U6.4 U7.4 VEE.2 | length 5488.9
  Top Layer w20: U7.4 v2(4215,4320) ; VEE.2 4239.71,3156.29 ccw(c4310.42,3227) 4310.42,3127 4592,3127 ccw(c4592,3152) 4617,3152 POWER.3 ; U5.4 v2(4714,4675) ; v2(4764,4223) 4831.59,4223 cw(c4831.59,4219.59) U6.4
  Bottom Layer w20: C52.2 C51.2 4215.88,4559.88 cw(c4251,4559.88) 4251,4595 4761,4595 ccw(c4761,4597) 4763,4597 ; POWER.3 4621,3210 4621,3197.25 4617,3197.25 4617,3158 ccw(c4647,3158) 4647,3128 5625,3128 ccw(c5625,3171) 5668,3171 5668,4426 ccw(c5611,4426) 5611,4483 4763,4483 ; C44.2 C43.2 4735,4675 cw(c4735,4647) 4763,4647 4763,4597 ; C47.2 cw(c4763.06,4165.06) 4761.56,4165.06 C48.2 ccw(c4761.56,4223.44) 4763,4223.44 4763,4483 ; 4763,4483 4763,4595 4763,4597
XTAL1: 16M.1 C2.1 U1.9 | length 666.5
  Top Layer w10: C2.1 3958,3657.56 16M.1 3958,3591 ccw(c3978.98,3591) 3978.98,3570.02 U1.9
XTAL2: 16M.2 C1.1 U1.10 | length 667.6
  Top Layer w10: C1.1 3956.56,3458.44 cw(c3956.56,3457) 16M.2 3958,3522 cw(c3980.43,3522) 3980.43,3544.43 U1.10
pads on no net: U1.1 U3.1 U3.3 U3.5 U3.7 U3.8 U4.1 U4.5 U4.8 U8.17 U9.17
copper on no net:
  other v3: 3230.83,3135.83 5789.17,3135.83 5789.17,4664.17 3230,4670

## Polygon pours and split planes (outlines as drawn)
AVSS on Bottom Layer "AVSS_BTU" (solid, pour order 11): 3120,3135.83 ccw(c3230.83,3135.83) 3230.83,3025 4085,3025 5781.01,3025 ccw(c5781.01,3143.99) 5900,3143.99 5900,4664.17 ccw(c5789.17,4664.17) 5789.17,4775 3230.83,4775 ccw(c3230.83,4664.17) 3120,4664.17
AVSS on Bottom Layer "AVSS_L02_P007" (solid, pour order 7): 4451,3582 4541,3582 4541,3260 4564,3260 cw(c4564,3259) 4565,3259 4565,3168 4470,3168 4470,3269 4448,3269
DGND on Bottom Layer "DGND_L02_P003" (solid, pour order 3): 5464.71,3568 5585.29,3568 cw(c5585.29,3528.59) 5624.71,3528.59 5624.71,3310.59 cw(c5590.56,3308.15) 5593,3274 5464.71,3274
DGND on Bottom Layer "DGND_L02_P002" (solid, pour order 2): 4869,3567 4559,3567 4559,3274 4871.54,3274
DGND on Bottom Layer "DGND_BTU" (solid, pour order 0): 4869,3567 cw(c4870,3567) 4870,3568 5464.71,3568 5464.71,3274 4868,3274
AVSS on Top Layer "AVSS_TOP" (solid, pour order 10): 3120,3135.83 ccw(c3230.83,3135.83) 3230.83,3025 4085,3025 5781.01,3025 ccw(c5781.01,3143.99) 5900,3143.99 5900,4664.17 ccw(c5789.17,4664.17) 5789.17,4775 3230.83,4775 ccw(c3230.83,4664.17) 3120,4664.17
AVSS on Top Layer "AVSS_L01_P006" (solid, pour order 6): 3862,3280 4066,3280 4066,3137 3863,3137
3V3 on Top Layer "3V3_L01_P005" (solid, pour order 5): 3688.5,3415 3860,3415 cw(c3860,3414) 3861,3414 3861,3290 3688,3290

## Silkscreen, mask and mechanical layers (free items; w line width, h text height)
Top Overlay:
  drawing of 1140 lines, arcs and shapes, not listed
  text "GPIO0" at 5395.55,3552.44 h40
  text "V5" at 5060.06,3545.67 h60
  text "V3" at 5260.06,3540.67 h60
Bottom Overlay:
  text "G" at 5011,3378.44 h40
  text "G" at 5110,3378.44 h40
  text "G" at 5212,3378.44 h40
  text "G" at 5312,3378.44 h40
  text "G" at 5411,3378.44 h40
  text "DIN" at 5026,3151 h40
  text "CS" at 5424,3151.44 h40
  text "DO" at 5122,3150.44 h40
  text "SCK" at 5235,3150.44 h40
  text "SYNC" at 5346,3149.44 h40
  text "+5" at 4443,3068.83 h60
  text "-5" at 4644,3068.67 h60
  text "G" at 4536,3067.67 h60
Bottom Solder:
  rectangle: 5500,4515 5605,4725
  rectangle: 3700,4520 3805,4730
Mechanical 1:
  lines w10: 3120,3135.83 ccw(c3230.83,3135.83) 3230.83,3025 4085,3025 5155,3025 5615,3025 5781.01,3025 ccw(c5781.01,3143.99) 5900,3143.99 5900,4664.17 ccw(c5789.17,4664.17) 5789.17,4775 3775,4775 3230.83,4775 ccw(c3230.83,4664.17) 3120,4664.17 3120,3135.83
